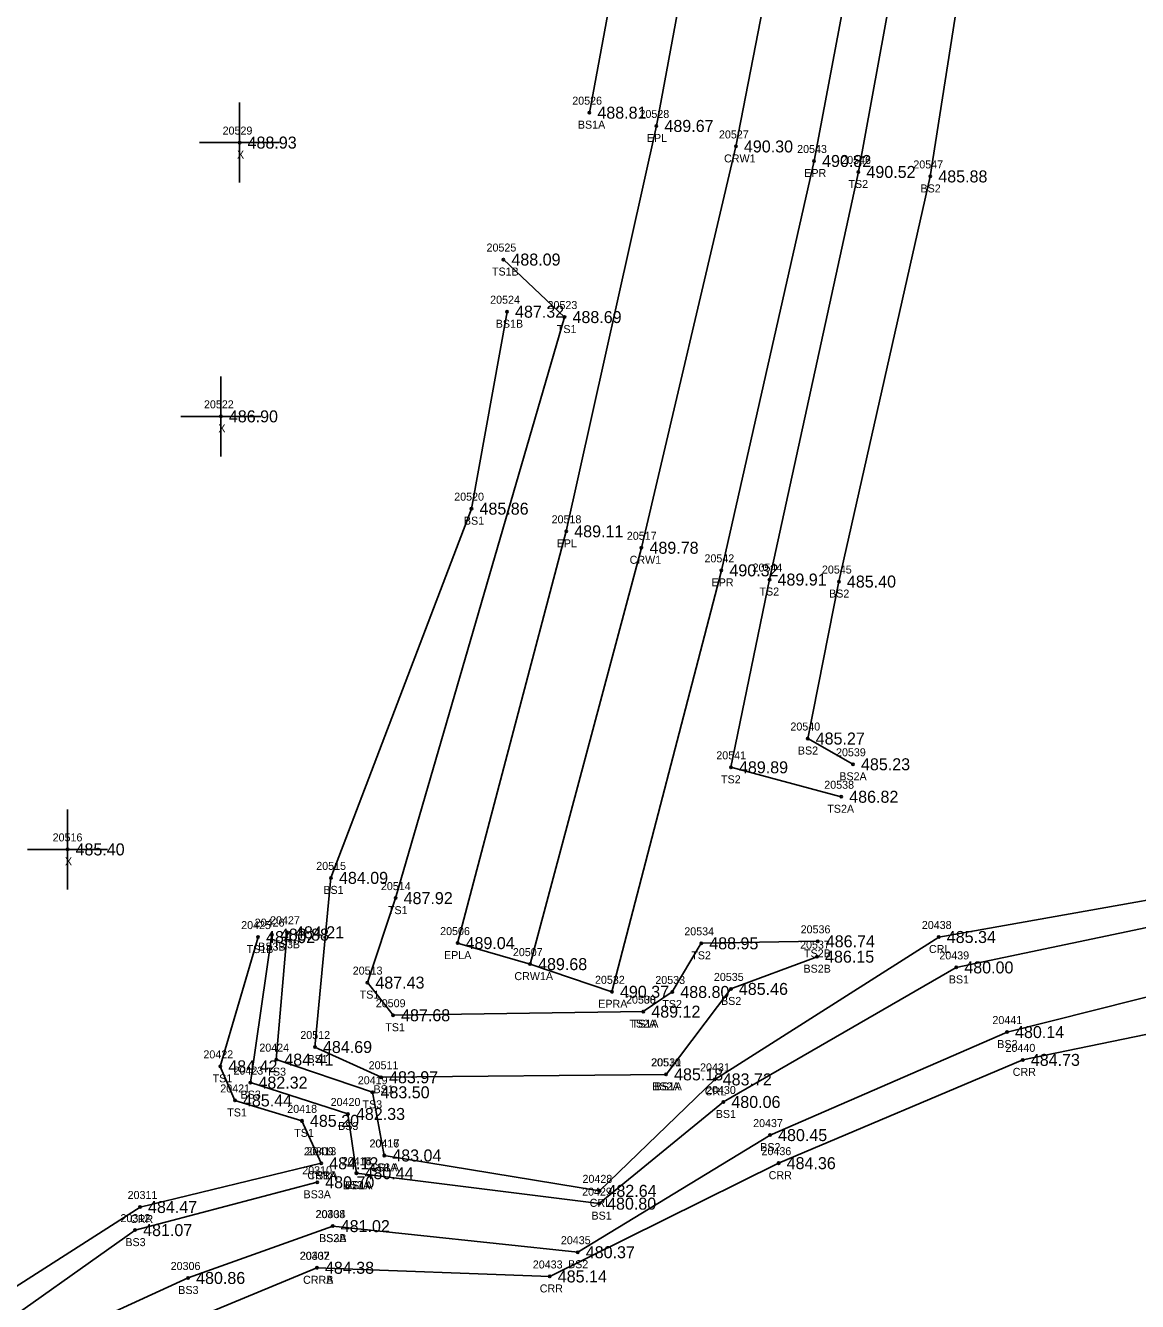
# Model space of a CAD drawing. Extents: x 1649406 to 1650436, y 896752 to 898178.
# Drawn here: x 1649831.9 to 1649970.8, y 897420.5 to 897580 of the extents above; entities that cross this region are included whole.
import ezdxf

# ---------------------------------------------------------------- set-up
doc = ezdxf.new("R2010")
doc.units = 0
for name, color, linetype in [('RD_DTM_BkLn1', 7, 'Continuous'), ('RD_DTM_BkLn2', 7, 'Continuous'), ('RD_DTM_BkLn_txCode', 7, 'Continuous'), ('RD_EX_H2O', 7, 'Continuous'), ('RD_EX_H2O_txCode', 7, 'Continuous'), ('RD_EX_Misc', 7, 'Continuous'), ('RD_EX_Misc_txCode', 7, 'Continuous'), ('RD_EX_Road', 7, 'Continuous'), ('RD_EX_Road_txCode', 7, 'Continuous'), ('RD_EX_TX_H2O_ELEV', 7, 'Continuous'), ('RD_EX_TX_Misc_ELEV', 7, 'Continuous'), ('RD_EX_TX_Road_ELEV', 7, 'Continuous'), ('RD_HC_Survey_ELEV', 7, 'Continuous'), ('RD_HC_Survey_txCode', 7, 'Continuous'), ('RD_SMD_Locator', 7, 'Continuous')]:
    doc.layers.add(name, color=color, linetype=linetype)

msp = doc.modelspace()

# ---------------------------------------------------------------- linework, layer by layer
at = {"layer": 'RD_DTM_BkLn1'}
msp.add_lwpolyline([(1649894.9, 897462.66), (1649908.82, 897514.7), (1649920.62, 897564.87), (1649930.21, 897614.13), (1649937.18, 897663.59), (1649942.29, 897713.83), (1649944.94, 897762.9), (1649945.25, 897813.29), (1649942.44, 897857.84), (1649938.23, 897907.76), (1649931.88, 897958.19), (1649923.51, 898006.94), (1649914.47, 898059.31), (1649904.54, 898110.23), (1649895.09, 898157.93)], dxfattribs=at)
at = {"layer": 'RD_DTM_BkLn2'}
for points in [[(1649902.31, 897569.09), (1649911.24, 897617.29), (1649920.65, 897666.08), (1649926.58, 897702.16), (1649928.32, 897715.46), (1649931.24, 897763.41), (1649931.43, 897814), (1649927.03, 897856.89), (1649923.37, 897907.61), (1649916.38, 897954.04), (1649907.99, 898004.31), (1649897.74, 898054.92), (1649893.88, 898075.41)], [(1649933.78, 897483.58), (1649920, 897487.26), (1649924.82, 897510.73), (1649935.93, 897561.68), (1649945.08, 897611.69), (1649952.32, 897661.64), (1649959.23, 897688.55), (1649963.85, 897688.77), (1649960.9, 897661.72)], [(1649935.25, 897487.64), (1649929.59, 897490.86), (1649933.49, 897510.48), (1649944.91, 897561.12), (1649952.72, 897611.11), (1649958.86, 897661.37), (1649961.49, 897688)], [(1649873.21, 897436.53), (1649903.52, 897432.72), (1649919.05, 897445.43), (1649948.16, 897462.25), (1649998.36, 897472.78), (1650066.66, 897490.8), (1650100.48, 897500.37), (1650137.22, 897517.85), (1650184.21, 897531.99), (1650196.44, 897519.92), (1650247.18, 897540.57), (1650293.31, 897540.96), (1650345.63, 897555.71), (1650381.77, 897576.92), (1650384.86, 897569.3), (1650418.68, 897572.17)], [(1649870.24, 897429.91), (1649900.86, 897426.65), (1649924.89, 897441.29), (1649954.5, 897454.17), (1650003.28, 897466.46), (1650067.47, 897482.78), (1650102.49, 897492.5), (1650136.77, 897511.64), (1650185.16, 897523.83), (1650191.93, 897513.41), (1650246.64, 897532.49), (1650295.05, 897532.6), (1650346.56, 897548.17), (1650378.24, 897567.88), (1650382.5, 897562.26), (1650420.79, 897565.67)], [(1649909.05, 897456.72), (1649877.78, 897456.27), (1649874.57, 897460.35), (1649878.1, 897470.91), (1649899.2, 897543.54), (1649891.57, 897550.73)], [(1649911.89, 897448.88), (1649876.28, 897448.52), (1649868.02, 897452.3), (1649870.02, 897473.44), (1649887.58, 897519.59), (1649892.02, 897544.21)], [(1649868.8, 897437.77), (1649866.39, 897443.07), (1649858.02, 897445.62), (1649856.19, 897449.88), (1649860.91, 897466.04)], [(1649873.21, 897436.53), (1649872.14, 897443.93), (1649859.96, 897447.85), (1649862.63, 897466.35)], [(1649876.68, 897438.74), (1649875.21, 897446.64), (1649863.19, 897450.72), (1649864.53, 897466.64)], [(1649909.05, 897456.72), (1649912.67, 897459.18), (1649916.29, 897465.26), (1649930.85, 897465.51)], [(1649911.89, 897448.88), (1649919.99, 897459.56), (1649930.76, 897463.59)], [(1649868.3, 897435.39), (1649845.55, 897429.41), (1649825.91, 897415.47), (1649821.11, 897400.31), (1649799.74, 897406.72), (1649785.82, 897395.65), (1649747.09, 897406.73), (1649737.33, 897411.73), (1649729.69, 897424.71), (1649738.08, 897430.82), (1649737.7, 897451.57)], [(1649604.6, 897005.75), (1649602.47, 897009.39), (1649602.3, 897017.91), (1649611.46, 897066.62), (1649609.91, 897087.35), (1649647.02, 897127.55), (1649667.48, 897155.95), (1649673.52, 897172.2), (1649701.06, 897200.6), (1649725.89, 897215.14), (1649740.6, 897244.69), (1649756.42, 897243.48), (1649789.18, 897306.38), (1649812.44, 897341.7), (1649825.72, 897367.05), (1649832.43, 897399.23), (1649835.49, 897415.79), (1649852.17, 897423.43), (1649870.24, 897429.91)]]:
    msp.add_lwpolyline(points, dxfattribs=at)
at = {"layer": 'RD_EX_H2O'}
for points in [[(1649876.68, 897438.74), (1649903.57, 897434.32), (1649917.97, 897448.25), (1649945.97, 897466.05), (1649997.07, 897475.13), (1650065.61, 897493.38), (1650098.97, 897502.84), (1650134.01, 897525.34), (1650184.58, 897534.43), (1650198.48, 897522.14), (1650246.85, 897542.98), (1650292.7, 897543.66), (1650345.21, 897558.55), (1650381.85, 897579.1), (1650386.65, 897572.92), (1650418.93, 897577.14)], [(1649868.27, 897424.7), (1649897.36, 897423.62), (1649925.96, 897437.78), (1649956.47, 897450.69), (1650000.97, 897459.86), (1650068.15, 897479.89), (1650103.08, 897490.82), (1650137.62, 897510.46), (1650180.41, 897516.6), (1650196.59, 897509.69), (1650246.91, 897526.88), (1650295.53, 897529.67), (1650347.35, 897546.47), (1650373.21, 897562.26), (1650385.6, 897559.55), (1650420.39, 897565.14)], [(1649868.8, 897437.77), (1649846.16, 897432.3), (1649822.76, 897417.33), (1649816.54, 897408.15), (1649799.76, 897408.66), (1649785.38, 897398.06), (1649752.08, 897411.48), (1649746.25, 897411.21), (1649738.94, 897415.88), (1649733.55, 897423.08), (1649741.13, 897430.63), (1649738.72, 897452.07)], [(1649610.78, 897003.58), (1649606.65, 897007.8), (1649603.49, 897018.01), (1649613.66, 897065.71), (1649613.8, 897087.62), (1649648.77, 897123.4), (1649673.15, 897145.36), (1649677.84, 897170.04), (1649704.36, 897195), (1649732.98, 897211.32), (1649741.05, 897244.13), (1649760.18, 897240.39), (1649790.48, 897304.8), (1649814.66, 897340.98), (1649827.92, 897366.62), (1649835.63, 897392.05), (1649839.2, 897413.36), (1649851.88, 897417.91), (1649868.27, 897424.7)]]:
    msp.add_lwpolyline(points, dxfattribs=at)
at = {"layer": 'RD_EX_Misc'}
for p, q in [((1649858.6, 897560.35), (1649858.6, 897570.35)), ((1649853.6, 897565.35), (1649863.6, 897565.35)), ((1649856.26, 897526.13), (1649856.26, 897536.13)), ((1649851.26, 897531.13), (1649861.26, 897531.13)), ((1649837.1, 897472), (1649837.1, 897482)), ((1649832.1, 897477), (1649842.1, 897477))]:
    msp.add_line(p, q, dxfattribs=at)
at = {"layer": 'RD_EX_Road'}
for points in [[(1649905.13, 897459.2), (1649918.81, 897511.88), (1649930.39, 897563.05), (1649939.7, 897612.37), (1649946.83, 897662.25), (1649952.14, 897712.87), (1649954.77, 897762.63), (1649955.64, 897791.88), (1649955.33, 897812.31), (1649952.46, 897859.75), (1649947.95, 897909.71), (1649941.78, 897959.51), (1649933.15, 898009.23), (1649924.03, 898060.85), (1649913.91, 898112.48), (1649904.76, 898159.93)], [(1649885.84, 897465.29), (1649899.42, 897516.76), (1649910.69, 897567.43), (1649919.68, 897616.11), (1649926.54, 897664.67), (1649931.97, 897714.33), (1649935.04, 897763.32), (1649935.22, 897813.54), (1649932.16, 897857.76), (1649927.73, 897907.79), (1649922.24, 897954.81), (1649913.41, 898005.06), (1649903.99, 898056.19), (1649899.68, 898079.2), (1649896.48, 898096.53), (1649894.5, 898108.47), (1649884.77, 898155.82)], [(1649905.13, 897459.2), (1649894.9, 897462.66), (1649885.84, 897465.29)]]:
    msp.add_lwpolyline(points, dxfattribs=at)
at = {"layer": 'RD_SMD_Locator'}
for centre in [(1649902.31, 897569.09), (1649910.69, 897567.43), (1649858.6, 897565.35), (1649920.62, 897564.87), (1649930.39, 897563.05), (1649935.93, 897561.68), (1649944.91, 897561.12), (1649891.57, 897550.73), (1649892.02, 897544.21), (1649899.2, 897543.54), (1649856.26, 897531.13), (1649887.58, 897519.59), (1649899.42, 897516.76), (1649908.82, 897514.7), (1649918.81, 897511.88), (1649924.82, 897510.73), (1649933.49, 897510.48), (1649929.59, 897490.86), (1649935.25, 897487.64), (1649920, 897487.26), (1649933.78, 897483.58), (1649837.1, 897477), (1649870.02, 897473.44), (1649878.1, 897470.91), (1649864.53, 897466.64), (1649860.91, 897466.04), (1649862.63, 897466.35), (1649885.84, 897465.29), (1649916.29, 897465.26), (1649930.85, 897465.51), (1649945.97, 897466.05), (1649930.76, 897463.59), (1649894.9, 897462.66), (1649948.16, 897462.25), (1649874.57, 897460.35), (1649905.13, 897459.2), (1649912.67, 897459.18), (1649919.99, 897459.56), (1649877.78, 897456.27), (1649909.05, 897456.72), (1649909.05, 897456.72), (1649954.5, 897454.17), (1649868.02, 897452.3), (1649863.19, 897450.72), (1649956.47, 897450.69), (1649856.19, 897449.88), (1649859.96, 897447.85), (1649876.28, 897448.52), (1649911.89, 897448.88), (1649911.89, 897448.88), (1649917.97, 897448.25), (1649875.21, 897446.64), (1649858.02, 897445.62), (1649919.05, 897445.43), (1649866.39, 897443.07), (1649872.14, 897443.93), (1649924.89, 897441.29), (1649876.68, 897438.74), (1649876.68, 897438.74), (1649868.8, 897437.77), (1649868.8, 897437.77), (1649873.21, 897436.53), (1649873.21, 897436.53), (1649925.96, 897437.78), (1649868.3, 897435.39), (1649903.57, 897434.32), (1649846.16, 897432.3), (1649903.52, 897432.72), (1649870.24, 897429.91), (1649870.24, 897429.91), (1649845.55, 897429.41), (1649900.86, 897426.65), (1649868.27, 897424.7), (1649868.27, 897424.7), (1649897.36, 897423.62), (1649852.17, 897423.43)]:
    msp.add_circle(centre, 0.15, dxfattribs=at)

# ---------------------------------------------------------------- texts
at = {"layer": 'RD_DTM_BkLn_txCode'}
for s, p in [('20526', (1649900.17, 897570.09)), ('BS1A', (1649900.87, 897567.09)), ('20546', (1649933.78, 897562.68)), ('20547', (1649942.79, 897562.12)), ('TS2', (1649934.68, 897559.68)), ('BS2', (1649943.68, 897559.12)), ('20525', (1649889.46, 897551.73)), ('TS1B', (1649890.14, 897548.73)), ('20524', (1649889.91, 897545.21)), ('20523', (1649897.08, 897544.54)), ('BS1B', (1649890.61, 897542.21)), ('TS1', (1649898.24, 897541.54)), ('20520', (1649885.42, 897520.59)), ('BS1', (1649886.63, 897517.59)), ('20544', (1649922.7, 897511.73)), ('20545', (1649931.37, 897511.48)), ('TS2', (1649923.57, 897508.73)), ('BS2', (1649932.26, 897508.48)), ('20540', (1649927.43, 897491.86)), ('20541', (1649918.17, 897488.26)), ('BS2', (1649928.36, 897488.86)), ('20539', (1649933.13, 897488.64)), ('TS2', (1649918.76, 897485.26)), ('BS2A', (1649933.54, 897485.64)), ('20538', (1649931.66, 897484.58)), ('TS2A', (1649932.04, 897481.58)), ('20515', (1649868.18, 897474.44)), ('BS1', (1649869.07, 897471.44)), ('20514', (1649876.26, 897471.91)), ('TS1', (1649877.14, 897468.91)), ('20426', (1649860.49, 897467.35)), ('20427', (1649862.41, 897467.64)), ('20425', (1649858.8, 897467.04)), ('20534', (1649914.17, 897466.26)), ('20536', (1649928.71, 897466.51)), ('BS3B', (1649860.93, 897464.35)), ('TS3B', (1649862.81, 897464.64)), ('20537', (1649928.64, 897464.59)), ('TS1B', (1649859.48, 897464.04)), ('TS2', (1649915.04, 897463.26)), ('TS2B', (1649929.13, 897463.51)), ('20439', (1649946.04, 897463.25)), ('20513', (1649872.74, 897461.35)), ('BS2B', (1649929.06, 897461.59)), ('20533', (1649910.55, 897460.18)), ('20535', (1649917.87, 897460.56)), ('BS1', (1649947.22, 897460.25)), ('TS1', (1649873.61, 897458.35)), ('20508', (1649906.89, 897457.72)), ('20530', (1649906.89, 897457.72)), ('20509', (1649875.62, 897457.27)), ('TS2', (1649911.42, 897457.18)), ('BS2', (1649918.76, 897457.56)), ('TS2A', (1649907.31, 897454.72)), ('TS1A', (1649907.6, 897454.72)), ('20441', (1649952.67, 897455.17)), ('20512', (1649866.19, 897453.3)), ('TS1', (1649876.81, 897454.27)), ('20424', (1649861.07, 897451.72)), ('BS2', (1649953.28, 897452.17)), ('20422', (1649854.08, 897450.88)), ('BS1', (1649867.08, 897450.3)), ('20510', (1649910.01, 897449.88)), ('20531', (1649910.05, 897449.88)), ('20423', (1649857.84, 897448.85)), ('TS3', (1649861.95, 897448.72)), ('20511', (1649874.73, 897449.52)), ('TS1', (1649855.23, 897447.88)), ('20421', (1649856.19, 897446.62)), ('20419', (1649873.37, 897447.64)), ('BS2A', (1649910.17, 897446.88)), ('BS1A', (1649910.45, 897446.88)), ('BS3', (1649858.73, 897445.85)), ('BS1', (1649875.33, 897446.52)), ('20430', (1649916.89, 897446.43)), ('TS1', (1649857.06, 897443.62)), ('20418', (1649864.56, 897444.07)), ('20420', (1649869.98, 897444.93)), ('TS3', (1649873.96, 897444.64)), ('BS1', (1649918.1, 897443.43)), ('BS3', (1649870.91, 897441.93)), ('20437', (1649922.77, 897442.29)), ('TS1', (1649865.43, 897441.07)), ('20413', (1649866.96, 897438.77)), ('20417', (1649874.85, 897439.74)), ('BS2', (1649923.66, 897439.29)), ('20414', (1649871.37, 897437.53)), ('20415', (1649871.37, 897437.53)), ('20310', (1649866.43, 897436.39)), ('TS1A', (1649867.35, 897435.77)), ('TS3A', (1649874.95, 897436.74)), ('BS3A', (1649871.49, 897434.53)), ('BS1A', (1649871.77, 897434.53)), ('BS3A', (1649866.59, 897433.39)), ('20429', (1649901.4, 897433.72)), ('20308', (1649868.08, 897430.91)), ('20434', (1649868.12, 897430.91)), ('BS1', (1649902.57, 897430.72)), ('20312', (1649843.72, 897430.41)), ('BS3', (1649844.33, 897427.41)), ('BS2A', (1649868.52, 897427.91)), ('BS3B', (1649868.54, 897427.91)), ('20435', (1649898.75, 897427.65)), ('20306', (1649849.99, 897424.43)), ('BS2', (1649899.64, 897424.65)), ('BS3', (1649850.94, 897421.43))]:
    msp.add_text(s, height=1, dxfattribs=at).set_placement(p)
at = {"layer": 'RD_EX_H2O_txCode'}
for s, p in [('20438', (1649943.85, 897467.05)), ('CRL', (1649944.74, 897464.05)), ('20440', (1649954.31, 897451.69)), ('20431', (1649916.14, 897449.25)), ('CRR', (1649955.21, 897448.69)), ('CRL', (1649916.74, 897446.25)), ('20309', (1649866.64, 897438.77)), ('20416', (1649874.82, 897439.74)), ('20436', (1649923.82, 897438.78)), ('CRRA', (1649867.06, 897435.77)), ('CRLA', (1649874.97, 897436.74)), ('CRR', (1649924.71, 897435.78)), ('20428', (1649901.45, 897435.32)), ('20311', (1649844.61, 897433.3)), ('CRL', (1649902.34, 897432.32)), ('CRR', (1649844.91, 897430.3)), ('20307', (1649866.11, 897425.7)), ('20432', (1649866.15, 897425.7)), ('20433', (1649895.24, 897424.62)), ('CRRA', (1649866.53, 897422.7)), ('CRRB', (1649866.54, 897422.7)), ('CRR', (1649896.11, 897421.62))]:
    msp.add_text(s, height=1, dxfattribs=at).set_placement(p)
at = {"layer": 'RD_EX_Misc_txCode'}
for s, p in [('20529', (1649856.48, 897566.35)), ('X', (1649858.28, 897563.35)), ('20522', (1649854.15, 897532.13)), ('X', (1649855.95, 897529.13)), ('20516', (1649835.24, 897478)), ('X', (1649836.78, 897475))]:
    msp.add_text(s, height=1, dxfattribs=at).set_placement(p)
at = {"layer": 'RD_EX_Road_txCode'}
for s, p in [('20528', (1649908.57, 897568.43)), ('EPL', (1649909.49, 897565.43)), ('20543', (1649928.27, 897564.05)), ('EPR', (1649929.16, 897561.05)), ('20518', (1649897.59, 897517.76)), ('EPL', (1649898.22, 897514.76)), ('20542', (1649916.69, 897512.88)), ('EPR', (1649917.58, 897509.88)), ('20506', (1649883.66, 897466.29)), ('EPLA', (1649884.14, 897463.29)), ('20532', (1649903.01, 897460.2)), ('EPRA', (1649903.42, 897457.2))]:
    msp.add_text(s, height=1, dxfattribs=at).set_placement(p)
at = {"layer": 'RD_EX_TX_H2O_ELEV'}
for s, p in [('485.34', (1649946.97, 897465.3)), ('484.73', (1649957.47, 897449.94)), ('483.72', (1649918.97, 897447.5)), ('484.12', (1649869.8, 897437.02)), ('483.04', (1649877.68, 897437.99)), ('484.36', (1649926.96, 897437.03)), ('482.64', (1649904.57, 897433.57)), ('484.47', (1649847.16, 897431.55)), ('484.38', (1649869.27, 897423.95)), ('484.38', (1649869.27, 897423.95)), ('485.14', (1649898.36, 897422.87))]:
    msp.add_text(s, height=1.5, dxfattribs=at).set_placement(p)
at = {"layer": 'RD_EX_TX_Misc_ELEV'}
for s, p in [('488.81', (1649903.31, 897568.34)), ('488.93', (1649859.6, 897564.6)), ('490.52', (1649936.93, 897560.93)), ('485.88', (1649945.91, 897560.37)), ('488.09', (1649892.57, 897549.98)), ('487.32', (1649893.02, 897543.46)), ('488.69', (1649900.2, 897542.79)), ('486.90', (1649857.26, 897530.38)), ('485.86', (1649888.58, 897518.84)), ('489.91', (1649925.82, 897509.98)), ('485.40', (1649934.49, 897509.73)), ('485.27', (1649930.59, 897490.11)), ('489.89', (1649921, 897486.51)), ('485.23', (1649936.25, 897486.89)), ('486.82', (1649934.78, 897482.83)), ('485.40', (1649838.1, 897476.25)), ('484.09', (1649871.02, 897472.69)), ('487.92', (1649879.1, 897470.16)), ('484.02', (1649861.91, 897465.29)), ('483.88', (1649863.63, 897465.6)), ('484.21', (1649865.53, 897465.89)), ('488.95', (1649917.29, 897464.51)), ('486.74', (1649931.85, 897464.76)), ('486.15', (1649931.76, 897462.84)), ('480.00', (1649949.16, 897461.5)), ('487.43', (1649875.57, 897459.6)), ('485.46', (1649920.99, 897458.81)), ('488.80', (1649913.67, 897458.43)), ('489.12', (1649910.05, 897455.97)), ('489.12', (1649910.05, 897455.97)), ('487.68', (1649878.78, 897455.52)), ('480.14', (1649955.5, 897453.42)), ('484.69', (1649869.02, 897451.55)), ('484.41', (1649864.19, 897449.97)), ('484.42', (1649857.19, 897449.13)), ('483.97', (1649877.28, 897447.77)), ('485.18', (1649912.89, 897448.13)), ('485.18', (1649912.89, 897448.13)), ('482.32', (1649860.96, 897447.1)), ('485.44', (1649859.02, 897444.87)), ('483.50', (1649876.21, 897445.89)), ('480.06', (1649920.05, 897444.68)), ('482.33', (1649873.14, 897443.18)), ('485.20', (1649867.39, 897442.32)), ('480.45', (1649925.89, 897440.54)), ('484.12', (1649869.8, 897437.02)), ('483.04', (1649877.68, 897437.99)), ('480.44', (1649874.21, 897435.78)), ('480.44', (1649874.21, 897435.78)), ('480.70', (1649869.3, 897434.64)), ('480.80', (1649904.52, 897431.97)), ('481.07', (1649846.55, 897428.66)), ('481.02', (1649871.24, 897429.16)), ('481.02', (1649871.24, 897429.16)), ('480.37', (1649901.86, 897425.9)), ('480.86', (1649853.17, 897422.68))]:
    msp.add_text(s, height=1.5, dxfattribs=at).set_placement(p)
at = {"layer": 'RD_EX_TX_Road_ELEV'}
for s, p in [('489.67', (1649911.69, 897566.68)), ('490.82', (1649931.39, 897562.3)), ('489.11', (1649900.42, 897516.01)), ('490.32', (1649919.81, 897511.13)), ('489.04', (1649886.84, 897464.54)), ('490.37', (1649906.13, 897458.45))]:
    msp.add_text(s, height=1.5, dxfattribs=at).set_placement(p)
at = {"layer": 'RD_HC_Survey_ELEV'}
for s, p in [('490.30', (1649921.62, 897564.12)), ('489.78', (1649909.82, 897513.95)), ('489.68', (1649895.9, 897461.91))]:
    msp.add_text(s, height=1.5, dxfattribs=at).set_placement(p)
at = {"layer": 'RD_HC_Survey_txCode'}
for s, p in [('20527', (1649918.5, 897565.87)), ('CRW1', (1649919.14, 897562.87)), ('20517', (1649906.99, 897515.7)), ('CRW1', (1649907.34, 897512.7)), ('20507', (1649892.75, 897463.66)), ('CRW1A', (1649892.94, 897460.66))]:
    msp.add_text(s, height=1, dxfattribs=at).set_placement(p)

doc.saveas('drawing.dxf')
